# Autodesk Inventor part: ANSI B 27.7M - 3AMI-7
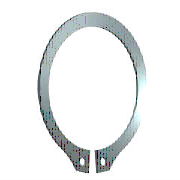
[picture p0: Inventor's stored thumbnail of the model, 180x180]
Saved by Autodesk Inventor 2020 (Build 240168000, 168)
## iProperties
Created: 2008-02
Part Number: ANSI B 27.7M - 3AMI-7
Material: Steel, Mild
Description: Metric Snap Ring
Document SubType Name: Modeling
Standard: ANSI B 27.7M
Designer: PN
Standards Organization: ANSI
Language: en-US
Size Designation: 3AMI-7
Categories: <MemberInstance><Categories><Category DisplayName="Shaft Parts" InternalName="7f7aeb1f-a693-4053-b835-cee3144e0d98" Mnemonic="SHFT"><Category DisplayName="Circl
Density: 7.86 g/cm^3
Mass: 0.16205 g
Surface Area: 1.07811 cm^2
Volume: 0.0206171 cm^3
Appearance: 179,145,89
IsCustomPart: 0
Author: PN
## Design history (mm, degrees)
body "Solid1"
sketch "Sketch2"
  geometry: L1 (-0.517, -6.359)-(-2.677, -6.359); L2 (-0.517, -3.259)-(-0.517, -6.359); L3 (0, -9.315)-(0, 7.036) reference; L4 (0.517, -6.359)-(2.677, -6.359); L5 (0.517, -3.259)-(0.517, -6.359); A1 r 3.3 centre (0, 0) between (0.517, -3.259) and (-0.517, -3.259); A2 r 4.233 centre (0, 0.467) between (3.873, -1.243) and (-3.873, -1.243); A3 r 14.206 centre (-16.869, -6.979) between (-2.677, -6.359) and (-3.873, -1.243); A4 r 14.206 centre (16.869, -6.979) between (3.873, -1.243) and (2.677, -6.359); 1 further point
  constraints: 9 point on circle, 9 symmetric about line, 8 end point, 4 centre point, 1 coincident, 1 horizontal, 1 point on line, 1 tangent, 1 vertical, 3 other
  dimensions: "d15" = 0.46667 distance of A2.centre A1.centre (= 0.333333 x b); "d28" = 6.6 diameter of A1 (= g1); "d32" = 1.4 dimension on A2 A1 (= b); "d34" = 3.1 distance of L2.start L1.start (= ParA); "d35" = 1.03333 distance between parallel lines of L5 L2 (= 0.333333 x ParA); "d48" = 2.16 distance of L1.start L1.end (= 1.8 x Diam5); "d49" = 0.62 distance from line of A3.centre L1 (= 0.2 x ParA)
extrude "Extrusion1" new body sketch "Sketch2" distance "d16" = 0.6 (= tt); taper "d17" = 0 deg
sketch "Sketch3"
  geometry: L1 (-0.517, -6.359)-(-2.677, -6.359) reference; L2 (0.517, -6.359)-(0.517, -3.259) reference; L3 (2.677, -6.359)-(0.517, -6.359) reference; L4 (0, -6.979)-(0, -2.639) reference; C1 r 0.6 at (-1.657, -4.809); C2 r 0.6 at (1.657, -4.809)
  constraints: 2 centre point, 1 symmetric about line, 1 other
  dimensions: "d36" = 1.2 diameter of C1 (= Diam5); "d37" = 1.55 distance from line of L1 C1.centre (= 0.5 x ParA); "d47" = 3.31333 diameter of C1.centre L4 (= 0.333333 x ParA + 1.9 x Diam5)
extrude "Extrusion2" cut sketch "Sketch3" extent not by distance; stored distance "d26" = 0.13; taper "d27" = 0 deg
other parameters: "g1" = 6.6 [user parameter; used in 1 equation term], "ParA" = 3.1 [user parameter; used in 5 equation terms], "b" = 1.4 [user parameter; used in 2 equation terms], "tt" = 0.6 [user parameter; used in 1 equation term], "Diam5" = 1.2 [user parameter; used in 3 equation terms], "d0" = 0 (derived), "d2" = 1.9 (derived), "d4" = 0.55 (derived), "d6" = 2.2 (derived), "d8" = 1.65 (derived), "d10" = 3.3 (derived), "d12" = 0.44 (derived), "d14" = 0.3 (derived), "d18" = 1.1 (derived), "d20" = 0.99 (derived), "d22" = 0.99 (derived), "d24" = 1 (derived), "d51" = 0, "d52" = 0, "d53" = 0, "d54" = 0, "TEMPLATE" = 12.345 [user parameter]
